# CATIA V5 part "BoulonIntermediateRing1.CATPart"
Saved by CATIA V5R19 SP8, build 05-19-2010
Part number: BoulonIntermediateRing1
Bounding box of the stored display mesh (mm): x -28 to 24, y 572 to 588, z 597 to 613
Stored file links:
  G:\EU_thinkMotion\CFAO_2010\MMS_groupe3\MMS_groupe3\A reprendre\fovide\fovide\BoulonIntermediateRing1.CATPart
  C:\Users\Rodger\Desktop\Part11.CATPart
  G:\EU_thinkMotion\CFAO_2010\MMS_groupe3\MMS_groupe3\A reprendre\fovide\fovide\fovide.CATProduct
  G:\EU_thinkMotion\CFAO_2010\MMS_groupe3\MMS_groupe3\A reprendre\fovide\fovide\Intermediate Ring 7.CATPart
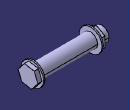
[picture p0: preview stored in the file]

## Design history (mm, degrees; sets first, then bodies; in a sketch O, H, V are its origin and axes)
Parameters
  Diametre = 10 mm
  Longueur = 40 mm
Set1
  DatumSurface1: linked copy from another document
  Point1: linked copy from another document
Body1 (main body)
Body2
  Sketch1 on DatumSurface1, origin (20, 0, -20), H (0, 1, 0), V (0, 0, 1)
    circle A1 centre (580, 625) radius 8
    point P1 (580, 625)
    reference projected point E1 (580, 625) from Point1
    radius A1 = 8 {= Diametre *8/10}
    coincidence: P1 E1
  Pad1: profile Sketch1, direction (1, 0, 0), length 1
  Sketch2 on end face of Pad1, origin (21, 0, -18), H (0, 1, 0), V (0, 0, 1)
    point P1 (580, 623)
    point P2 (582.4939, 616.4593)
    point P3 (586.9113, 621.8894)
    point P4 (584.4175, 628.4301)
    point P5 (577.5061, 629.5407)
    point P6 (573.0887, 624.1106)
    point P7 (575.5825, 617.5699)
    point P8 (584.7026, 619.1744)
    line L1 (582.4939, 616.4593) -> (586.9113, 621.8894)
    line L2 (586.9113, 621.8894) -> (584.4175, 628.4301)
    line L3 (584.4175, 628.4301) -> (577.5061, 629.5407)
    line L4 (577.5061, 629.5407) -> (573.0887, 624.1106)
    line L5 (573.0887, 624.1106) -> (575.5825, 617.5699)
    line L6 (575.5825, 617.5699) -> (582.4939, 616.4593)
    construction line L7 (580, 623) -> (584.7026, 619.1744)
    construction circle A1 centre (580, 623) radius 7
    construction arc A2 centre (573.0887, 624.1106) radius 7 from (577.5061, 629.5407) to (575.5825, 617.5699) cw
    construction arc A3 centre (586.9113, 621.8894) radius 7 from (584.4175, 628.4301) to (582.4939, 616.4593) ccw
    reference projected point E1 (580, 623) from Point1
    radius A1 = 7 {= Diametre *7/10}
    coincidence: A1 P2, A1 P3, A1 P4, A1 P5, A1 P6, A1 P7, A2 P1, A3 P1, P1 E1
    midpoint: P8 L1
    parallelism: L1 L4
  Pad2: profile Sketch2, direction (1, 0, 0), length 3
  Sketch3 on start face of Pad1, origin (20, 0, -20), H (0, -1, 0), V (0, 0, 1)
    circle A1 centre (-580, 625) radius 5
    point P1 (-580, 625)
    reference projected point E1 (-580, 625) from Point1
    radius A1 = 5 {= Diametre /2}
    coincidence: P1 E1
  Pad3: profile Sketch3, direction (-1, 0, 0), length 40 {= Longueur}
  Sketch4 on end face of Pad3, origin (-20, 0, -100), H (0, -1, 0), V (0, 0, 1)
    circle A1 centre (-580, 705) radius 8
    point P1 (-580, 705)
    reference projected point E1 (-580, 705) from Point1
    radius A1 = 8 {= Diametre *8/10}
    coincidence: P1 E1
  Pad4: profile Sketch4, direction (-1, 0, 0), length 1
  Sketch5 on end face of Pad4, origin (-21, 0, -102), H (0, -1, 0), V (0, 0, 1)
    point P1 (-580, 707)
    point P2 (-580.0478, 700.0002)
    point P3 (-573.9619, 703.4587)
    point P4 (-573.9141, 710.4585)
    point P5 (-579.9522, 713.9998)
    point P6 (-586.0381, 710.5413)
    point P7 (-586.0859, 703.5415)
    point P8 (-577.0048, 701.7294)
    line L1 (-580.0478, 700.0002) -> (-573.9619, 703.4587)
    line L2 (-573.9619, 703.4587) -> (-573.9141, 710.4585)
    line L3 (-573.9141, 710.4585) -> (-579.9522, 713.9998)
    line L4 (-579.9522, 713.9998) -> (-586.0381, 710.5413)
    line L5 (-586.0381, 710.5413) -> (-586.0859, 703.5415)
    line L6 (-586.0859, 703.5415) -> (-580.0478, 700.0002)
    construction line L7 (-580, 707) -> (-577.0048, 701.7294)
    construction circle A1 centre (-580, 707) radius 7
    construction arc A2 centre (-586.0381, 710.5413) radius 7 from (-579.9522, 713.9998) to (-586.0859, 703.5415) cw
    construction arc A3 centre (-573.9619, 703.4587) radius 7 from (-573.9141, 710.4585) to (-580.0478, 700.0002) ccw
    reference projected point E1 (-580, 707) from Point1
    radius A1 = 7 {= Diametre *7/10}
    coincidence: A1 P2, A1 P3, A1 P4, A1 P5, A1 P6, A1 P7, A2 P1, A3 P1, P1 E1
    midpoint: P8 L1
    parallelism: L1 L4
  Pad5: profile Sketch5, direction (-1, 0, 0), length 3
  Sketch6 on end face of Pad5, origin (-24, 0, -108), H (0, -1, 0), V (0, 0, 1)
    circle A1 centre (-580, 713) radius 5
    point P1 (-580, 713)
    reference projected point E1 (-580, 713) from Point1
    radius A1 = 5 {= Diametre /2}
    coincidence: P1 E1
  Pad6: profile Sketch6, direction (-1, 0, 0), length 4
